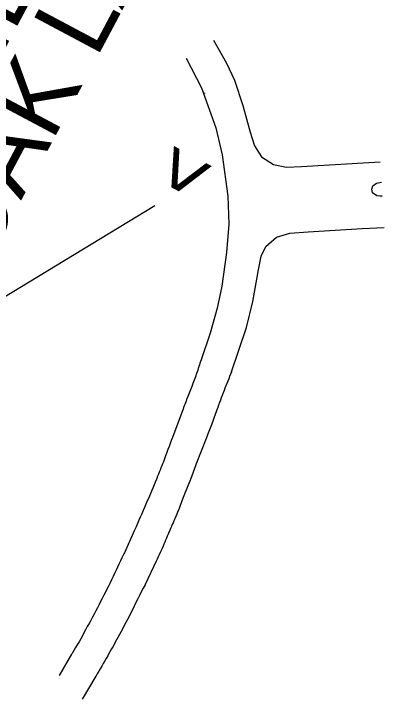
# Model space of a CAD drawing. Extents: x 1970823 to 1988115, y 770601 to 786368.
# Drawn here: x 1977296 to 1977542.7, y 781517.3 to 781978.5 of the extents above; entities that cross this region are included whole.
import ezdxf

# ---------------------------------------------------------------- set-up
doc = ezdxf.new("R2010")
doc.units = 0
for name, color, linetype in [('CTL Sheet Text', 7, 'Continuous'), ('CTL Supplemental Horizontal and Vertical Text', 7, 'Continuous'), ('Old_Level_3', 7, 'Continuous'), ('Old_Level_57', 7, 'Continuous')]:
    doc.layers.add(name, color=color, linetype=linetype)

msp = doc.modelspace()

# ---------------------------------------------------------------- linework, layer by layer
at = {"layer": 'CTL Supplemental Horizontal and Vertical Text'}
msp.add_lwpolyline([(1977166.09, 781695.38), (1977179.92, 781721.33), (1977390.98, 781849.5)], dxfattribs=at)
at = {"layer": 'Old_Level_3'}
for points in [[(1977430.47, 781960.62), (1977439.24, 781945.32), (1977444.57, 781933.75), (1977450.23, 781916.69), (1977455.16, 781898.79), (1977457.98, 781889.71), (1977462.77, 781882.31), (1977470.96, 781877.02), (1977479.71, 781875.39), (1977489.68, 781875.79), (1977508.49, 781876.89), (1977542.73, 781878.79)], [(1977412.13, 781948.61), (1977422.33, 781928.73), (1977431.96, 781901.78), (1977436.19, 781883.68), (1977440.1, 781855.74), (1977440.7, 781836.87), (1977439.26, 781817.92), (1977436.07, 781795.17), (1977432.9, 781780.45), (1977428.16, 781763.59), (1977422.07, 781745.73)], [(1977424.39, 781925.29), (1977424.43, 781924.84)], [(1977544.04, 781855.77), (1977542.4, 781855.7), (1977540.31, 781855.94), (1977537.42, 781857.98), (1977536.94, 781860.49), (1977537.74, 781862.75), (1977540.21, 781864.61), (1977543.5, 781865.24)], [(1977442.58, 781737.63), (1977452.6, 781767.39), (1977456.9, 781784.87), (1977460.83, 781806.25), (1977462.46, 781815.5), (1977465.7, 781822.01), (1977472.84, 781828.26), (1977481.74, 781830.98), (1977494.27, 781831.88), (1977530.56, 781833.92), (1977545.24, 781834.65)], [(1977409.14, 781710.32), (1977402.81, 781693.42)], [(1977425.58, 781692.79), (1977418.87, 781675.67)], [(1977377.36, 781631.12), (1977370.49, 781615.79)], [(1977391.95, 781610.15), (1977384.53, 781594.51)], [(1977334.93, 781547.57), (1977326.51, 781533.2)], [(1977351.3, 781532.76), (1977342.16, 781517.25)]]:
    msp.add_lwpolyline(points, dxfattribs=at)
for points in [[(1977422.07, 781745.73), (1977419.05, 781736.46), (1977412.37, 781718.86), (1977409.14, 781710.32)], [(1977442.58, 781737.63), (1977437.56, 781724.97), (1977432.71, 781712), (1977429.02, 781701.93), (1977425.58, 781692.79)], [(1977402.81, 781693.42), (1977396.71, 781677.08), (1977392.29, 781665.89), (1977385, 781648.58), (1977377.36, 781631.12)], [(1977418.87, 781675.67), (1977415.26, 781665.77), (1977409.91, 781652.55), (1977406.06, 781642.52), (1977401.61, 781632.23), (1977397.12, 781621.72), (1977391.95, 781610.15)], [(1977370.49, 781615.79), (1977369.87, 781614.57), (1977361.87, 781597.68), (1977353.41, 781580.98), (1977344.39, 781564), (1977335.25, 781548.08), (1977334.88, 781547.49)], [(1977384.53, 781594.51), (1977384.44, 781594.35), (1977374.67, 781575.07), (1977366.05, 781558.77), (1977359.25, 781546.55), (1977351.22, 781532.63)]]:
    msp.add_spline(points, degree=3, dxfattribs=at)

# ---------------------------------------------------------------- texts
at = {"layer": 'CTL Sheet Text'}
for s, p in [('(WILLOW', (1977247.06, 781873.86)), ('OAK LANE)', (1977276.44, 781806.71))]:
    msp.add_text(s, height=50, rotation=61.9832, dxfattribs=at).set_placement(p)
at = {"layer": 'Old_Level_57'}
msp.add_text('>', height=39.13, rotation=241.9613, dxfattribs=at).set_placement((1977401.25, 781893.85))

doc.saveas('drawing.dxf')
